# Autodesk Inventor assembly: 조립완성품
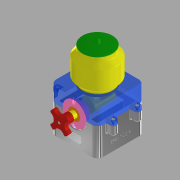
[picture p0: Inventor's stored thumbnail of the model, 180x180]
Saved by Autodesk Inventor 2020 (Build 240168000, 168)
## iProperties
Created: 2022-03
Part Number: 조립완성품
Document SubType Name: Assembly
Designer: Administrator
Author: Administrator
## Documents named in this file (11)
- C:\Users\Administrator\Documents\Inventor\720306V1023\조립완성품.iam
- C:\Users\Administrator\Documents\Inventor\720306V1023\본체.ipt
- C:\Users\Administrator\Documents\Inventor\720306V1023\720306V1023 (1)\베어링 부시.ipt
- C:\Users\Administrator\Documents\Inventor\720306V1023\720306V1023 (1)\본체커버.ipt
- C:\Users\Administrator\Documents\Inventor\720306V1023\720306V1023 (1)\볼트 M3x12.ipt
- C:\Users\Administrator\Documents\Inventor\720306V1023\720306V1023 (1)\볼트 M4x12.ipt
- C:\Users\Administrator\Documents\Inventor\720306V1023\720306V1023 (1)\앞커버.ipt
- C:\Users\Administrator\Documents\Inventor\720306V1023\720306V1023 (1)\용기.ipt
- C:\Users\Administrator\Documents\Inventor\720306V1023\720306V1023 (1)\용기캡.ipt
- C:\Users\Administrator\Documents\Inventor\720306V1023\720306V1023 (1)\핸들.ipt
- C:\Users\Administrator\Documents\Inventor\720306V1023\720306V1023 (1)\핸들축.ipt
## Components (2 placed, 2 different names)
1. 핸들:1
2. 핸들축:1 — 각도:1
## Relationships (1: Angle 1)
- 각도:1 [Angle]: 핸들축:1
